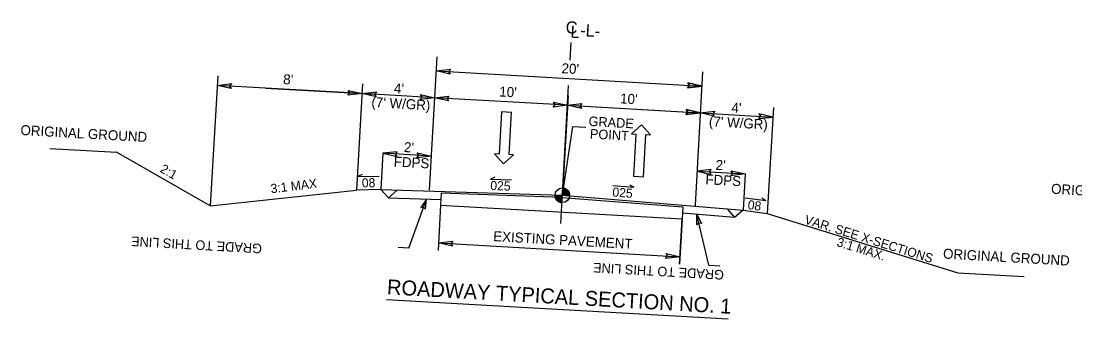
# Model space of a CAD drawing. Extents: x 2604316 to 2606605, y 617090 to 619543.
# Drawn here: x 2605218 to 2605915, y 617130 to 617327 of the extents above; entities that cross this region are included whole.
import ezdxf

# ---------------------------------------------------------------- set-up
doc = ezdxf.new("R2010")
doc.units = 0
for name, color, linetype in [('Exist XS Ground Line', 7, 'Continuous'), ('Pattern 1', 7, 'Continuous'), ('Prop Vertical Profile Curve Label', 7, 'Continuous'), ('Typical Grade Point Symbol CELL', 7, 'Continuous'), ('Typical Pavement Slope CELL', 7, 'Continuous'), ('Typical Pavement Slope Information CELL', 7, 'Continuous'), ('Typical Terminator CELL', 7, 'Continuous'), ('Typical Text Centerline CELL', 7, 'Continuous'), ('Typical Text General CELL', 7, 'Continuous')]:
    doc.layers.add(name, color=color, linetype=linetype)

msp = doc.modelspace()

# ---------------------------------------------------------------- linework, layer by layer
at = {"layer": 'Exist XS Ground Line'}
for p, q in [((2605496.02, 617212.88), (2605495.56, 617204.89)), ((2605575.98, 617209.93), (2605496.02, 617212.88)), ((2605495.56, 617204.89), (2605655.31, 617195.79)), ((2605575.98, 617209.93), (2605655.76, 617203.78)), ((2605655.76, 617203.78), (2605655.31, 617195.79)), ((2605655.76, 617203.78), (2605655.31, 617195.79))]:
    msp.add_line(p, q, dxfattribs=at)
at = {"layer": 'Pattern 1'}
for p, q in [((2605237.28, 617242.46), (2605281.21, 617239.96)), ((2605837.58, 617160.19), (2605881.5, 617157.69))]:
    msp.add_line(p, q, dxfattribs=at)
at = {"layer": 'Prop Vertical Profile Curve Label'}
for p, q in [((2605343.29, 617204.37), (2605281.21, 617239.96)), ((2605343.29, 617204.37), (2605440.04, 617214.88)), ((2605456.09, 617215.25), (2605440.04, 617214.88)), ((2605456.09, 617215.25), (2605576.07, 617211.42)), ((2605456.09, 617215.25), (2605461.21, 617209.74)), ((2605466.78, 617214.91), (2605461.21, 617209.74)), ((2605576.07, 617211.42), (2605695.7, 617201.61)), ((2605461.21, 617209.74), (2605495.78, 617208.64)), ((2605474.52, 617176.59), (2605486.27, 617208.94)), ((2605689.99, 617196.71), (2605655.52, 617199.54)), ((2605673, 617165.29), (2605665, 617198.76)), ((2605685.04, 617202.48), (2605689.99, 617196.71)), ((2605695.7, 617201.61), (2605689.99, 617196.71)), ((2605695.7, 617201.61), (2605711.6, 617199.42)), ((2605711.6, 617199.42), (2605837.58, 617160.19)), ((2605474.52, 617176.59), (2605467.41, 617177)), ((2605673, 617165.29), (2605680.11, 617164.88))]:
    msp.add_line(p, q, dxfattribs=at)
at = {"layer": 'Typical Grade Point Symbol CELL'}
for p, q in [((2605571.24, 617211.7), (2605576.07, 617211.42)), ((2605575.78, 617206.6), (2605576.07, 617211.42)), ((2605576.07, 617211.42), (2605575.78, 617206.6)), ((2605576.07, 617211.42), (2605576.34, 617216.25)), ((2605580.89, 617211.15), (2605576.07, 617211.42))]:
    msp.add_line(p, q, dxfattribs=at)
for points in [[(2605571.26, 617211.7), (2605571.23, 617211.17)], [(2605571.36, 617211.69), (2605571.3, 617210.6)], [(2605571.45, 617211.69), (2605571.37, 617210.25)], [(2605571.55, 617211.68), (2605571.45, 617209.96)], [(2605571.65, 617211.68), (2605571.54, 617209.72)], [(2605571.74, 617211.67), (2605571.62, 617209.52)], [(2605571.84, 617211.67), (2605571.71, 617209.33)], [(2605571.94, 617211.66), (2605571.79, 617209.15)], [(2605572.03, 617211.65), (2605571.88, 617208.99)], [(2605572.13, 617211.65), (2605571.97, 617208.85)], [(2605572.23, 617211.64), (2605572.06, 617208.72)], [(2605572.32, 617211.64), (2605572.15, 617208.59)], [(2605572.42, 617211.63), (2605572.24, 617208.47)], [(2605572.52, 617211.63), (2605572.33, 617208.36)], [(2605572.61, 617211.62), (2605572.42, 617208.24)], [(2605572.71, 617211.62), (2605572.51, 617208.14)], [(2605572.81, 617211.61), (2605572.6, 617208.05)], [(2605572.9, 617211.6), (2605572.7, 617207.96)], [(2605573, 617211.6), (2605572.79, 617207.87)], [(2605573.1, 617211.59), (2605572.88, 617207.79)], [(2605573.19, 617211.59), (2605572.97, 617207.71)], [(2605573.29, 617211.58), (2605573.06, 617207.64)], [(2605573.39, 617211.58), (2605573.16, 617207.57)], [(2605573.48, 617211.57), (2605573.25, 617207.5)], [(2605573.58, 617211.57), (2605573.34, 617207.43)], [(2605573.67, 617211.56), (2605573.44, 617207.37)], [(2605573.77, 617211.56), (2605573.53, 617207.31)], [(2605573.87, 617211.55), (2605573.62, 617207.25)], [(2605573.96, 617211.54), (2605573.72, 617207.2)], [(2605574.06, 617211.54), (2605573.81, 617207.15)], [(2605574.16, 617211.53), (2605573.91, 617207.1)], [(2605574.25, 617211.53), (2605574, 617207.06)], [(2605574.35, 617211.52), (2605574.09, 617207.01)], [(2605574.45, 617211.52), (2605574.19, 617206.97)], [(2605574.54, 617211.51), (2605574.28, 617206.93)], [(2605574.64, 617211.51), (2605574.38, 617206.89)], [(2605574.74, 617211.5), (2605574.47, 617206.87)], [(2605574.83, 617211.49), (2605574.57, 617206.83)], [(2605574.93, 617211.49), (2605574.66, 617206.8)], [(2605575.03, 617211.48), (2605574.76, 617206.78)], [(2605575.12, 617211.48), (2605574.85, 617206.75)], [(2605575.22, 617211.47), (2605574.95, 617206.72)], [(2605575.32, 617211.47), (2605575.04, 617206.71)], [(2605575.41, 617211.46), (2605575.14, 617206.68)], [(2605575.51, 617211.46), (2605575.24, 617206.66)], [(2605575.61, 617211.45), (2605575.33, 617206.65)], [(2605575.7, 617211.45), (2605575.43, 617206.63)], [(2605575.8, 617211.44), (2605575.52, 617206.62)], [(2605575.89, 617211.43), (2605575.62, 617206.61)], [(2605575.99, 617211.43), (2605575.72, 617206.6), (2605575.72, 617206.6)], [(2605576.38, 617216.25), (2605576.38, 617216.25), (2605576.11, 617211.42)], [(2605576.48, 617216.24), (2605576.21, 617211.42)], [(2605576.58, 617216.23), (2605576.3, 617211.41)], [(2605576.67, 617216.22), (2605576.4, 617211.41)], [(2605576.77, 617216.2), (2605576.5, 617211.4)], [(2605576.86, 617216.19), (2605576.59, 617211.39)], [(2605576.96, 617216.17), (2605576.69, 617211.39)], [(2605577.06, 617216.16), (2605576.78, 617211.38)], [(2605577.15, 617216.14), (2605576.88, 617211.38)], [(2605577.25, 617216.11), (2605576.98, 617211.37)], [(2605577.34, 617216.09), (2605577.07, 617211.37)], [(2605577.44, 617216.06), (2605577.17, 617211.36)], [(2605577.53, 617216.03), (2605577.27, 617211.36)], [(2605577.63, 617215.99), (2605577.36, 617211.35)], [(2605577.72, 617215.97), (2605577.46, 617211.35)], [(2605577.82, 617215.93), (2605577.56, 617211.34)], [(2605577.91, 617215.89), (2605577.65, 617211.33)], [(2605578.01, 617215.85), (2605577.75, 617211.33)], [(2605578.1, 617215.81), (2605577.85, 617211.32)], [(2605578.2, 617215.76), (2605577.94, 617211.32)], [(2605578.29, 617215.71), (2605578.04, 617211.31)], [(2605578.38, 617215.66), (2605578.14, 617211.31)], [(2605578.48, 617215.61), (2605578.23, 617211.3)], [(2605578.57, 617215.55), (2605578.33, 617211.3)], [(2605578.67, 617215.49), (2605578.43, 617211.29)], [(2605578.76, 617215.44), (2605578.52, 617211.28)], [(2605578.85, 617215.38), (2605578.62, 617211.28)], [(2605578.95, 617215.31), (2605578.72, 617211.27)], [(2605579.04, 617215.24), (2605578.81, 617211.27)], [(2605579.13, 617215.16), (2605578.91, 617211.26)], [(2605579.22, 617215.09), (2605579.01, 617211.26)], [(2605579.32, 617215.01), (2605579.1, 617211.25)], [(2605579.41, 617214.91), (2605579.2, 617211.25)], [(2605579.5, 617214.82), (2605579.29, 617211.24)], [(2605579.59, 617214.73), (2605579.39, 617211.24)], [(2605579.68, 617214.63), (2605579.49, 617211.23)], [(2605579.77, 617214.53), (2605579.58, 617211.22)], [(2605579.86, 617214.41), (2605579.68, 617211.22)], [(2605579.95, 617214.29), (2605579.78, 617211.21)], [(2605580.04, 617214.17), (2605579.87, 617211.21)], [(2605580.13, 617214.03), (2605579.97, 617211.2)], [(2605580.22, 617213.89), (2605580.07, 617211.2)], [(2605580.31, 617213.73), (2605580.16, 617211.19)], [(2605580.4, 617213.57), (2605580.26, 617211.19)], [(2605580.48, 617213.39), (2605580.36, 617211.18)], [(2605580.57, 617213.18), (2605580.45, 617211.17)], [(2605580.65, 617212.95), (2605580.55, 617211.17)], [(2605580.73, 617212.68), (2605580.65, 617211.16)], [(2605580.81, 617212.34), (2605580.74, 617211.16)], [(2605580.88, 617211.84), (2605580.84, 617211.15)]]:
    msp.add_lwpolyline(points, dxfattribs=at)
msp.add_circle((2605576.06, 617211.43), 4.83, dxfattribs=at)
for start, end in [(176.73073, 266.73073), (356.73073, 86.73073)]:
    msp.add_arc((2605576.06, 617211.43), 4.83, start, end, dxfattribs=at)
at = {"layer": 'Typical Pavement Slope CELL'}
for p, q in [((2605493.14, 617303.01), (2605488.12, 617214.83)), ((2605348.19, 617290.49), (2605343.29, 617204.37)), ((2605492.6, 617293.59), (2605668.32, 617283.58)), ((2605668.85, 617293), (2605663.83, 617204.82)), ((2605668.85, 617293), (2605663.83, 617204.82)), ((2605443.67, 617278.64), (2605347.83, 617284.1)), ((2605379.78, 617282.28), (2605451.66, 617278.19)), ((2605444.04, 617285.03), (2605440.04, 617214.88)), ((2605491.6, 617275.92), (2605443.67, 617278.64)), ((2605579.45, 617270.91), (2605491.6, 617275.92)), ((2605579.82, 617277.3), (2605576.13, 617212.58)), ((2605535.84, 617266.63), (2605534.25, 617238.68)), ((2605542.43, 617266.26), (2605535.84, 617266.63)), ((2605540.84, 617238.3), (2605542.43, 617266.26)), ((2605579.45, 617270.91), (2605659.32, 617266.36)), ((2605579.45, 617270.91), (2605667.31, 617265.91)), ((2605715.6, 617269.57), (2605711.6, 617199.42)), ((2605667.31, 617265.91), (2605715.23, 617263.18)), ((2605582.83, 617256.95), (2605576.07, 617211.42)), ((2605582.83, 617256.95), (2605591.61, 617256.45)), ((2605628.5, 617258.02), (2605621.75, 617252.1)), ((2605621.75, 617252.1), (2605624.74, 617251.93)), ((2605634.33, 617251.38), (2605628.5, 617258.02)), ((2605624.74, 617251.93), (2605623.15, 617223.97)), ((2605629.74, 617223.6), (2605631.33, 617251.55)), ((2605631.33, 617251.55), (2605634.33, 617251.38)), ((2605457.45, 617239.17), (2605456.09, 617215.25)), ((2605489.4, 617237.35), (2605457.45, 617239.17)), ((2605534.25, 617238.68), (2605531.25, 617238.85)), ((2605531.25, 617238.85), (2605537.08, 617232.21)), ((2605537.08, 617232.21), (2605543.83, 617238.13)), ((2605543.83, 617238.13), (2605540.84, 617238.3)), ((2605443.79, 617225.17), (2605440.92, 617223.75)), ((2605665.12, 617227.35), (2605697.06, 617225.53)), ((2605697.06, 617225.53), (2605695.7, 617201.61)), ((2605440.92, 617223.75), (2605454.92, 617224.07)), ((2605531.49, 617223.43), (2605528.54, 617222.18)), ((2605528.54, 617222.18), (2605542.53, 617221.67)), ((2605609.49, 617217.87), (2605623.45, 617216.8)), ((2605620.66, 617218.37), (2605623.45, 617216.8)), ((2605623.15, 617223.97), (2605629.74, 617223.6)), ((2605495.56, 617204.89), (2605493.86, 617174.94)), ((2605663.92, 617206.42), (2605663.8, 617204.22)), ((2605696.86, 617209.86), (2605710.73, 617207.95)), ((2605708.04, 617209.68), (2605710.73, 617207.95)), ((2605653.6, 617165.84), (2605655.31, 617195.79)), ((2605655.31, 617195.79), (2605653.6, 617165.84)), ((2605494.14, 617179.93), (2605653.88, 617170.83)), ((2605459.74, 617142.61), (2605685.76, 617129.73))]:
    msp.add_line(p, q, dxfattribs=at)
at = {"layer": 'Typical Terminator CELL'}
for points in [[(2605501.87, 617291.44), (2605492.6, 617293.59), (2605502.11, 617294.71), (2605500.82, 617293.12)], [(2605357.1, 617281.96), (2605347.83, 617284.1), (2605357.33, 617285.23), (2605356.04, 617283.64)], [(2605434.41, 617280.79), (2605443.67, 617278.64), (2605434.17, 617277.52), (2605435.46, 617279.11)], [(2605659.05, 617285.72), (2605668.32, 617283.58), (2605658.81, 617282.45), (2605660.1, 617284.05)], [(2605658.87, 617282.5), (2605668.32, 617283.58), (2605659, 617285.78), (2605660.1, 617284.05)], [(2605452.94, 617276.5), (2605443.67, 617278.64), (2605453.18, 617279.77), (2605451.89, 617278.18)], [(2605482.33, 617278.06), (2605491.6, 617275.92), (2605482.09, 617274.79), (2605483.38, 617276.38)], [(2605500.86, 617273.77), (2605491.6, 617275.92), (2605501.1, 617277.04), (2605499.81, 617275.45)], [(2605570.19, 617273.06), (2605579.45, 617270.91), (2605569.95, 617269.78), (2605571.24, 617271.38)], [(2605588.72, 617268.77), (2605579.45, 617270.91), (2605588.96, 617272.04), (2605587.67, 617270.44)], [(2605658.05, 617268.05), (2605667.31, 617265.91), (2605657.81, 617264.78), (2605659.1, 617266.38)], [(2605657.86, 617264.83), (2605667.31, 617265.91), (2605658, 617268.11), (2605659.1, 617266.38)], [(2605676.58, 617263.76), (2605667.31, 617265.91), (2605676.82, 617267.04), (2605675.53, 617265.44)], [(2605705.78, 617262.1), (2605715.23, 617263.18), (2605705.92, 617265.38), (2605707.02, 617263.65)], [(2605466.9, 617240.25), (2605457.45, 617239.17), (2605466.77, 617236.97), (2605465.67, 617238.71)], [(2605480.13, 617239.5), (2605489.4, 617237.35), (2605479.9, 617236.23), (2605481.19, 617237.82)], [(2605674.57, 617228.43), (2605665.12, 617227.35), (2605674.43, 617225.15), (2605673.33, 617226.88)], [(2605687.8, 617227.67), (2605697.06, 617225.53), (2605687.56, 617224.4), (2605688.85, 617225.99)], [(2605485.55, 617202.22), (2605486.27, 617208.94), (2605482.44, 617203.31), (2605484.3, 617203.53)], [(2605664.95, 617192), (2605665, 617198.76), (2605668.17, 617192.73), (2605666.34, 617193.16)], [(2605503.41, 617177.79), (2605494.14, 617179.93), (2605503.65, 617181.06), (2605502.36, 617179.46)], [(2605644.62, 617172.98), (2605653.88, 617170.83), (2605644.38, 617169.71), (2605645.67, 617171.3)]]:
    msp.add_lwpolyline(points, close=True, dxfattribs=at)
at = {"layer": 'Typical Text Centerline CELL'}
for p, q in [((2605581.17, 617300.82), (2605581.84, 617312.5)), ((2605575.01, 617192.88), (2605580.21, 617284.11))]:
    msp.add_line(p, q, dxfattribs=at)

# ---------------------------------------------------------------- texts
at = {"layer": 'Typical Pavement Slope CELL'}
for s, height, rotation, p in [("20'", 6.6, 356.74026, (2605575.42, 617292.18)), ("8'", 6.6, 356.74026, (2605391.34, 617284.93)), ("4'", 6.6, 356.74026, (2605464.55, 617278.89)), ("10'", 6.6, 356.74026, (2605534.24, 617276.79)), ("(7' W/GR)", 6.6, 356.74026, (2605449.7, 617269.82)), ("10'", 6.6, 356.74026, (2605614.11, 617272.24)), ("4'", 6.6, 356.74026, (2605687.72, 617266.18)), ("(7' W/GR)", 6.6, 356.74026, (2605672.87, 617257.11)), ("2'", 6.6, 356.74026, (2605471.19, 617240.04)), ('FDPS', 6.6, 356.74026, (2605464.44, 617230.51)), ("2'", 6.6, 356.74026, (2605677.29, 617228.31)), ('FDPS', 6.6, 356.74026, (2605670.53, 617218.77)), ('VAR. SEE X-SECTIONS', 6, 342.70401, (2605735.77, 617192.87)), ('EXISTING PAVEMENT', 6.6, 356.74026, (2605530.23, 617181.18)), ('3:1 MAX.', 6, 342.70401, (2605757.03, 617178.01)), ('ROADWAY TYPICAL SECTION NO. 1', 9.9, 356.74026, (2605459.94, 617146.04))]:
    msp.add_text(s, height=height, rotation=rotation, dxfattribs=at).set_placement(p)
at = {"layer": 'Typical Pavement Slope Information CELL'}
for s, rotation, p in [('2:1', 330.17521, (2605309.53, 617227.18)), ('3:1 MAX', 6.95095, (2605383.56, 617212.75)), ('08', 1.31418, (2605443.57, 617216.61)), ('025', 357.88602, (2605528.36, 617214.98)), ('025', 355.59449, (2605609.02, 617210.69)), ('08', 352.16633, (2605698.34, 617202.38))]:
    msp.add_text(s, height=6, rotation=rotation, dxfattribs=at).set_placement(p)
at = {"layer": 'Typical Text Centerline CELL'}
for s, rotation, p in [('C', 356.74026, (2605578.1, 617318.61)), ('L', 356.68716, (2605581.27, 617315.62)), ('-L-', 356.68716, (2605587.75, 617316.67))]:
    msp.add_text(s, height=8, rotation=rotation, dxfattribs=at).set_placement(p)
at = {"layer": 'Typical Text General CELL'}
for s, height, rotation, p in [('GRADE', 6.302, 356.74026, (2605593.26, 617257.34)), ('ORIGINAL GROUND', 6.6, 356.74026, (2605217.62, 617251.35)), ('POINT', 6.302, 356.74026, (2605594.16, 617249.01)), ('ORIGINAL GROUND', 6.6, 356.74026, (2605899.12, 617212.54)), ('GRADE TO THIS LINE', 6.302, 176.74026, (2605377.59, 617179.3)), ('ORIGINAL GROUND', 6.6, 356.74026, (2605827.68, 617169.68)), ('GRADE TO THIS LINE', 6.302, 176.74026, (2605683.09, 617161.9))]:
    msp.add_text(s, height=height, rotation=rotation, dxfattribs=at).set_placement(p)

doc.saveas('drawing.dxf')
